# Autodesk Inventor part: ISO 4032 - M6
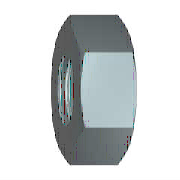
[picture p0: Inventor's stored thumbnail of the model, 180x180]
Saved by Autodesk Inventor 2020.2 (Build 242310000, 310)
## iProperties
Created: 2019-01
Part Number: ISO 4032 - M6
Material: Edelstahl, 440C
Description: Sechskantmutter. Produktklasse A und B
Document SubType Name: Modeling
Standard: DIN EN ISO 4032
Designer: lutzd
Standard Revision: 2013-04
Standards Organization: DIN
Language: de-DE
Size Designation: M6
Categories: <MemberInstance><Categories><Category DisplayName="Verbindungselemente" InternalName="e4da775c-781d-43d5-af7c-5136215cf5a6" Mnemonic="FSTN"><Category DisplayNam
Density: 7.75 g/cm^3
Appearance: Halbpoliert
IsCustomPart: 0
Author: lutzd
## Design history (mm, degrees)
sketch "Skizze1"
  geometry: L1 (-5.774, 0)-(-2.887, 5); L2 (-2.887, 5)-(2.887, 5); L3 (2.887, 5)-(5.774, 0); L4 (5.774, 0)-(2.887, -5); L5 (2.887, -5)-(-2.887, -5); L6 (-2.887, -5)-(-5.774, 0); 2 further points
  constraints: 12 end point, 1 coincident, 1 horizontal, 11 other
  dimensions: "d0" = 11.54701 distance of L3.end L1.start (= 1.1547 x SW)
extrude "Körper" new body sketch "Skizze1" distance "d1" = 5.2 (= KOH); taper "d2" = 0 deg
sketch "Skizze2"
  geometry: L1 (0, 2.887)-(0, 5.774) reference; L2 (0, 5.774)-(5.2, 5.774) reference; L3 (5.2, 2.887)-(5.2, 5.774) reference; L4 (-1.04, 0)-(6.24, 0) reference; L5 (0.764, 5.774)-(0, 4.45); L6 (4.436, 5.774)-(5.2, 4.45)
  constraints: 4 end point, 4 point on line
  dimensions: "d3" = 30 deg angle of L1 L5 (= ANG1); "d4" = 30 deg angle of L3 L6 (= ANG2); "d5" = 8.9 diameter of L5.end L4 (= SW0); "d6" = 8.9 diameter of L6.end L4 (= SW01)
revolve "Fase1" sketch "Skizze2" stored, may be unused: angle "d7" = 90 deg
sketch "Skizze3"
  geometry: 4 further points
  constraints: 1 coincident, 1 other
hole "Gewinde" sketch "Skizze3" at (0, 0) diameter "d25" = 4.917; stored, may be unused: countersink angle "d29" = 82 deg, drill point angle "d31" = 118 deg; dims "d26" = 6, "d27" = 4, "d28" = 2, "d30" = 8
workaxis "Work Axis1"
workplane "Work Plane1"
body "Solid1"
chamfer "Fase2" distance "d8" = 0.54127 (= -0.5 x GD1 + 0.5 x NND); stored, may be unused: angle "d9" = 30 deg, second distance "d40" = 0.54127 (= -0.5 x GD1 + 0.5 x NND)
chamfer "Fase3" distance "d10" = 0.54127 (= -0.5 x GD1 + 0.5 x NND); stored, may be unused: angle "d11" = 30 deg, second distance "d41" = 0.54127 (= -0.5 x GD1 + 0.5 x NND)
other parameters: "ANG1" = 30 deg [user parameter; used in 1 equation term], "ANG2" = 30 deg [user parameter; used in 1 equation term], "NND" = 6 [user parameter; used in 4 equation terms], "KOH" = 5.2 [user parameter; used in 1 equation term], "SW0" = 8.9 [user parameter; used in 1 equation term], "SW01" = 8.9 [user parameter; used in 1 equation term], "GD1" = 4.91747 (computed from THREADDIA, PTC, TOA) [user parameter; used in 4 equation terms], "d13" = 0, "d14" = 0, "d39" = 0, "d42" = 0, "GUL" = 0.54127 (= 0.541266 x PTC) [user parameter], "THREADDIA" = 6 [user parameter; used in 1 equation term], "TOA" = 30 deg [user parameter; used in 1 equation term], "PTC" = 1 [user parameter; used in 4 equation terms], "E0" = 11.55 (= 1.155 x SW) [user parameter], "GAL" = 0.54127 (= 0.541266 x PTC) [user parameter]
